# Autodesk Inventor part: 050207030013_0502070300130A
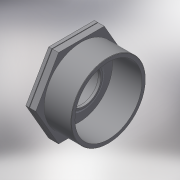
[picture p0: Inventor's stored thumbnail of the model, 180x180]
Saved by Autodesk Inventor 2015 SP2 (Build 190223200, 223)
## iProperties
Created: 2017-05
Part Number: 050207030013_0502070300130A
Material: Generic
Description: PLASSON REDUCING BUSHING 3"-1.1/4"
Document SubType Name: Modeling
Designer: KIM
Density: 1 g/cm^3
Appearance: Default
Author: KIM
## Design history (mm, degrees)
derived "050207.ipt"
feature "Solid1::050207.ipt"
tag "TaggingFeature1"
body "Solid1"
other parameters: "d1" = 87.884, "d5" = 32, "d8" = 0.48, "d12" = 0, "d15" = 48, "d19" = 0, "d30" = 9.6, "d31" = 4.8, "d33" = 38.952, "d34" = 79.0956, "d36" = 4.5, "d37" = 46.7424, "d38" = 31.68, "d39" = 35.0568, "d40" = 3.2, "d41" = 0, "H_" = 48, "R_" = 87.884, "l_2" = 32, "Rp_" = 38.952
